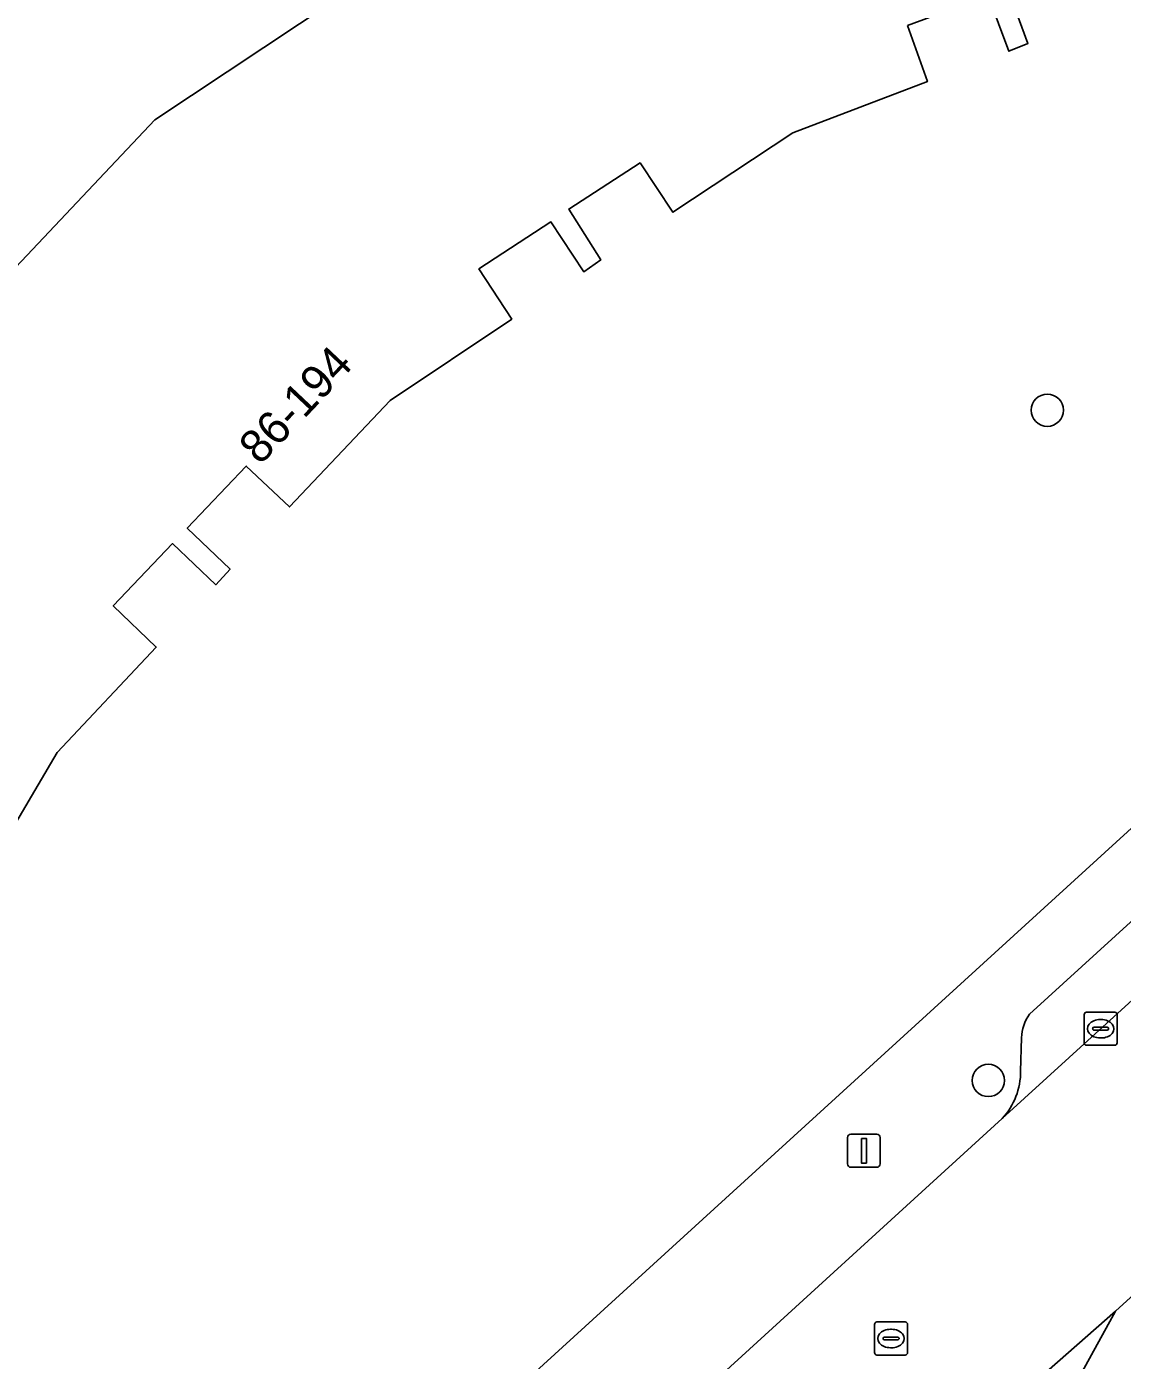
# Model space of a CAD drawing. Extents: x 163147 to 163550, y 380933 to 381639.
# Drawn here: x 163214.06 to 163247.22, y 381253.16 to 381293.5 of the extents above; entities that cross this region are included whole.
import ezdxf

# ---------------------------------------------------------------- set-up
doc = ezdxf.new("R2010")
doc.units = 0
for name, color, linetype in [('IMGEO_Boom', 7, 'Continuous'), ('IMGEO_Erf', 7, 'Continuous'), ('IMGEO_Kolk', 7, 'Continuous'), ('IMGEO_Lichtmast', 7, 'Continuous'), ('IMGEO_Pand', 7, 'Continuous'), ('IMGEO_Pand_nummerreeks', 7, 'Continuous'), ('IMGEO_Parkeervlak_open', 7, 'Continuous'), ('IMGEO_Rijbaan_lokaal_open', 7, 'Continuous'), ('IMGEO_Rioolput', 7, 'Continuous'), ('IMGEO_Voetpad_open', 7, 'Continuous')]:
    doc.layers.add(name, color=color, linetype=linetype)

msp = doc.modelspace()

# ---------------------------------------------------------------- linework, layer by layer
at = {"layer": 'IMGEO_Boom'}
for centre in [(163244.945, 381281.901), (163243.161, 381261.625)]:
    msp.add_circle(centre, 0.489, dxfattribs=at)
at = {"layer": 'IMGEO_Erf'}
for points in [[(163198.814, 381224.874), (163226.368, 381250), (163269.177, 381289.036), (163267.999, 381290.328), (163270.661, 381292.68), (163258.396, 381383.641)], [(163180.341, 381214.735), (163180.515, 381215.288), (163175.366, 381216.905), (163175.232, 381216.475), (163174.945, 381216.565), (163176.478, 381221.446), (163177.976, 381226.217), (163180.368, 381233.834), (163180.637, 381233.769), (163180.507, 381233.34), (163182.46, 381232.721), (163183.126, 381234.823), (163186.309, 381233.814), (163186.257, 381233.642), (163187.968, 381233.07), (163193.271, 381250), (163197.467, 381263.396), (163206.151, 381278.206), (163217.937, 381290.687), (163232.209, 381300.168)], [(163243.744, 381294.68), (163244.36, 381292.993), (163243.782, 381292.76), (163243.155, 381294.447)], [(163240.716, 381293.537), (163241.318, 381291.843), (163237.243, 381290.295), (163233.616, 381287.89), (163232.621, 381289.384), (163230.464, 381287.988), (163231.434, 381286.446), (163230.917, 381286.089), (163229.925, 381287.599), (163227.746, 381286.177), (163228.737, 381284.659), (163225.055, 381282.196), (163222.016, 381278.976), (163220.707, 381280.212), (163218.918, 381278.33), (163220.215, 381277.093), (163219.787, 381276.62), (163218.477, 381277.865), (163216.681, 381275.981), (163217.981, 381274.734), (163214.984, 381271.543), (163212.779, 381267.801)]]:
    msp.add_lwpolyline(points, dxfattribs=at)
at = {"layer": 'IMGEO_Kolk'}
for p, q in [((163246.059, 381262.764), (163246.059, 381263.616)), ((163246.134, 381263.69), (163246.986, 381263.69)), ((163247.06, 381263.616), (163247.06, 381262.764)), ((163246.318, 381263.184), (163246.318, 381263.196)), ((163246.756, 381263.147), (163246.358, 381263.147)), ((163246.361, 381263.233), (163246.759, 381263.233)), ((163246.547, 381263.47), (163246.572, 381263.47)), ((163246.802, 381263.196), (163246.802, 381263.184)), ((163246.986, 381262.69), (163246.134, 381262.69)), ((163246.57, 381262.91), (163246.545, 381262.91))]:
    msp.add_line(p, q, dxfattribs=at)
for points in [[(163246.059, 381262.764), (163246.059, 381263.616)], [(163246.134, 381263.69), (163246.986, 381263.69)], [(163247.06, 381263.616), (163247.06, 381262.764)], [(163246.986, 381262.69), (163246.134, 381262.69)]]:
    msp.add_lwpolyline(points, dxfattribs=at)
for centre, radius, start, end in [((163246.136, 381263.614), 0.0765, 91.552, 178.448), ((163246.136, 381263.614), 0.0765, 91.552, 178.448), ((163246.984, 381263.614), 0.0765, 1.552, 88.448), ((163246.984, 381263.614), 0.0765, 1.552, 88.448), ((163246.358, 381263.193), 0.0403, 85.8775, 175.7526), ((163246.355, 381263.183), 0.0366, 178.938, 274.7102), ((163246.759, 381263.19), 0.043, 264.8664, 352.4533), ((163246.763, 381263.195), 0.0386, 1.7309, 96.639), ((163246.136, 381262.766), 0.0765, 181.552, 268.448), ((163246.136, 381262.766), 0.0765, 181.552, 268.448), ((163246.984, 381262.766), 0.0765, 271.552, 358.448), ((163246.984, 381262.766), 0.0765, 271.552, 358.448)]:
    msp.add_arc(centre, radius, start, end, dxfattribs=at)
for centre, major_axis, ratio, start_param, end_param in [((163246.546, 381263.19), (-0.387, 0.002), 0.722429, 4.712389, 7.853982), ((163246.571, 381263.19), (-0.39, 0.002), 0.717154, 1.570796, 4.712389)]:
    msp.add_ellipse(centre, major_axis=major_axis, ratio=ratio, start_param=start_param, end_param=end_param, dxfattribs=at)
at = {"layer": 'IMGEO_Lichtmast'}
for p, q in [((163238.9, 381259.099), (163238.9, 381259.899)), ((163238.9, 381259.899), (163238.9, 381259.099)), ((163239, 381259.999), (163239.79, 381259.999)), ((163239.79, 381259.999), (163239, 381259.999)), ((163239.89, 381259.899), (163239.89, 381259.099)), ((163239.89, 381259.099), (163239.89, 381259.899)), ((163239.79, 381258.999), (163239, 381258.999)), ((163239, 381258.999), (163239.79, 381258.999))]:
    msp.add_line(p, q, dxfattribs=at)
msp.add_lwpolyline([(163239.32, 381259.874), (163239.47, 381259.874), (163239.47, 381259.124), (163239.32, 381259.124), (163239.32, 381259.874)], dxfattribs=at)
for centre, start, end in [((163239, 381259.899), 90, 180), ((163239, 381259.899), 90, 180), ((163239.79, 381259.899), 0, 90), ((163239.79, 381259.899), 360, 90), ((163239, 381259.099), 180, 270), ((163239, 381259.099), 180, 270), ((163239.79, 381259.099), 270, 0), ((163239.79, 381259.099), 270, 0)]:
    msp.add_arc(centre, 0.1, start, end, dxfattribs=at)
at = {"layer": 'IMGEO_Pand'}
for points in [[(163240.716, 381293.537), (163243.155, 381294.447), (163243.782, 381292.76), (163244.36, 381292.993), (163243.744, 381294.68), (163246.173, 381295.568), (163246.81, 381293.9), (163250.906, 381295.46), (163255.213, 381296.02), (163254.98, 381297.813), (163258.126, 381298.127), (163257.423, 381303.614), (163261.09, 381304.861), (163260.276, 381310.898), (163261.455, 381311.047), (163261.412, 381311.334), (163257.895, 381310.852)], [(163232.209, 381300.168), (163217.937, 381290.687), (163206.151, 381278.206)], [(163212.779, 381267.801), (163214.984, 381271.543), (163217.981, 381274.734), (163216.681, 381275.981), (163218.477, 381277.865), (163219.787, 381276.62), (163220.215, 381277.093), (163218.918, 381278.33), (163220.707, 381280.212), (163222.016, 381278.976), (163225.055, 381282.196), (163228.737, 381284.659), (163227.746, 381286.177), (163229.925, 381287.599), (163230.917, 381286.089), (163231.434, 381286.446), (163230.464, 381287.988), (163232.621, 381289.384), (163233.616, 381287.89), (163237.243, 381290.295), (163241.318, 381291.843), (163240.716, 381293.537)]]:
    msp.add_lwpolyline(points, dxfattribs=at)
at = {"layer": 'IMGEO_Parkeervlak_open'}
for points in [[(163243.582, 381260.479), (163269.371, 381283.951), (163270.465, 381284.947)], [(163267.264, 381284.445), (163244.41, 381263.628)], [(163244.164, 381262.916), (163244.138, 381261.908)]]:
    msp.add_lwpolyline(points, dxfattribs=at)
for centre, radius, start, end in [((163245.458, 381262.867), 1.295, 144.0344, 177.845), ((163242.049, 381261.898), 2.089, 317.2077, 0.272)]:
    msp.add_arc(centre, radius, start, end, dxfattribs=at)
at = {"layer": 'IMGEO_Rijbaan_lokaal_open'}
msp.add_lwpolyline([(163256.395, 381263.184), (163261.385, 381267.72), (163269.336, 381274.944), (163272.106, 381277.464), (163273.84, 381279.042), (163269.371, 381283.951), (163243.582, 381260.479), (163233.963, 381251.702), (163232.1, 381250), (163219.487, 381238.478), (163223.919, 381233.668), (163235.706, 381244.458), (163238.786, 381247.234), (163239.4, 381247.963), (163247.004, 381254.649)], close=True, dxfattribs=at)
msp.add_lwpolyline([(163245.557, 381252), (163247.004, 381254.649), (163239.4, 381247.963), (163238.786, 381247.234)], dxfattribs=at)
at = {"layer": 'IMGEO_Rioolput'}
for p, q in [((163239.715, 381253.393), (163239.715, 381254.245)), ((163239.79, 381254.319), (163240.642, 381254.319)), ((163240.716, 381254.245), (163240.716, 381253.393)), ((163239.974, 381253.813), (163239.974, 381253.825)), ((163240.017, 381253.862), (163240.415, 381253.862)), ((163240.203, 381254.099), (163240.228, 381254.099)), ((163240.458, 381253.825), (163240.458, 381253.813)), ((163240.412, 381253.776), (163240.014, 381253.776)), ((163240.226, 381253.539), (163240.201, 381253.539)), ((163240.642, 381253.319), (163239.79, 381253.319))]:
    msp.add_line(p, q, dxfattribs=at)
for points in [[(163239.715, 381253.393), (163239.715, 381254.245)], [(163239.79, 381254.319), (163240.642, 381254.319)], [(163240.716, 381254.245), (163240.716, 381253.393)], [(163240.642, 381253.319), (163239.79, 381253.319)]]:
    msp.add_lwpolyline(points, dxfattribs=at)
for centre, radius, start, end in [((163239.792, 381254.243), 0.0765, 91.552, 178.448), ((163239.792, 381254.243), 0.0765, 91.552, 178.448), ((163240.64, 381254.243), 0.0765, 1.552, 88.448), ((163240.64, 381254.243), 0.0765, 1.552, 88.448), ((163240.014, 381253.822), 0.0403, 85.8775, 175.7526), ((163240.011, 381253.812), 0.0366, 178.938, 274.7102), ((163240.415, 381253.819), 0.043, 264.8664, 352.4533), ((163240.419, 381253.824), 0.0386, 1.7309, 96.639), ((163239.792, 381253.395), 0.0765, 181.552, 268.448), ((163239.792, 381253.395), 0.0765, 181.552, 268.448), ((163240.64, 381253.395), 0.0765, 271.552, 358.448), ((163240.64, 381253.395), 0.0765, 271.552, 358.448)]:
    msp.add_arc(centre, radius, start, end, dxfattribs=at)
for centre, major_axis, ratio, start_param, end_param in [((163240.202, 381253.819), (-0.387, 0.002), 0.722429, 4.712389, 7.853982), ((163240.227, 381253.819), (-0.39, 0.002), 0.717154, 1.570796, 4.712389)]:
    msp.add_ellipse(centre, major_axis=major_axis, ratio=ratio, start_param=start_param, end_param=end_param, dxfattribs=at)
at = {"layer": 'IMGEO_Voetpad_open'}
for points in [[(163274.445, 381294.744), (163273.542, 381295.213), (163270.661, 381292.68), (163267.999, 381290.328), (163269.177, 381289.036), (163226.368, 381250), (163198.814, 381224.874), (163198.345, 381224.43), (163196.155, 381222.433), (163195.966, 381221.793), (163195.623, 381221.889), (163184.654, 381211.837), (163184.293, 381211.571), (163180.662, 381208.276), (163184.073, 381206.12), (163198.3, 381219.123)], [(163281.963, 381286.424), (163281.482, 381285.994), (163276.429, 381281.397), (163273.84, 381279.042), (163272.106, 381277.464), (163269.336, 381274.944), (163261.385, 381267.72), (163256.395, 381263.184), (163247.004, 381254.649), (163245.557, 381252)], [(163244.41, 381263.628), (163267.264, 381284.445)], [(163244.138, 381261.908), (163244.164, 381262.916)], [(163233.963, 381251.702), (163243.582, 381260.479)]]:
    msp.add_lwpolyline(points, dxfattribs=at)
for centre, radius, start, end in [((163245.458, 381262.867), 1.295, 144.0344, 177.845), ((163242.049, 381261.898), 2.089, 317.2077, 0.272)]:
    msp.add_arc(centre, radius, start, end, dxfattribs=at)

# ---------------------------------------------------------------- texts
at = {"layer": 'IMGEO_Pand_nummerreeks'}
msp.add_text('86-194', height=1, rotation=46.656, dxfattribs=at).set_placement((163221.125, 381280.217))

doc.saveas('drawing.dxf')
